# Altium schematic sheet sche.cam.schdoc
size 297 x 209 mm; Width: 1170; Height: 825; Symbol: Sheet-Symbol_A4; Company: 嘉立创EDA; Version: V1.0; Page Size: A4; @Project Name: 木马派(Mumap) Linux卡片电脑-RV1106G; @Page Count: 10; @Update Date: 2024-12-29; @Create Date: 2024-11-27; @Schematic Name: Schematic1; @Page No: 8; @Page Name: CSI; Border: 1; Title Block Position: 3; Region Start: 1; X Region Count: 6; Y Region Count: 4; Blade Width: 10; Title Block: 1; @Board Name: NandFlash; @Create Time: 22:20:09; @Update Time: 16:11:56; Device: Sheet-Symbol_A4
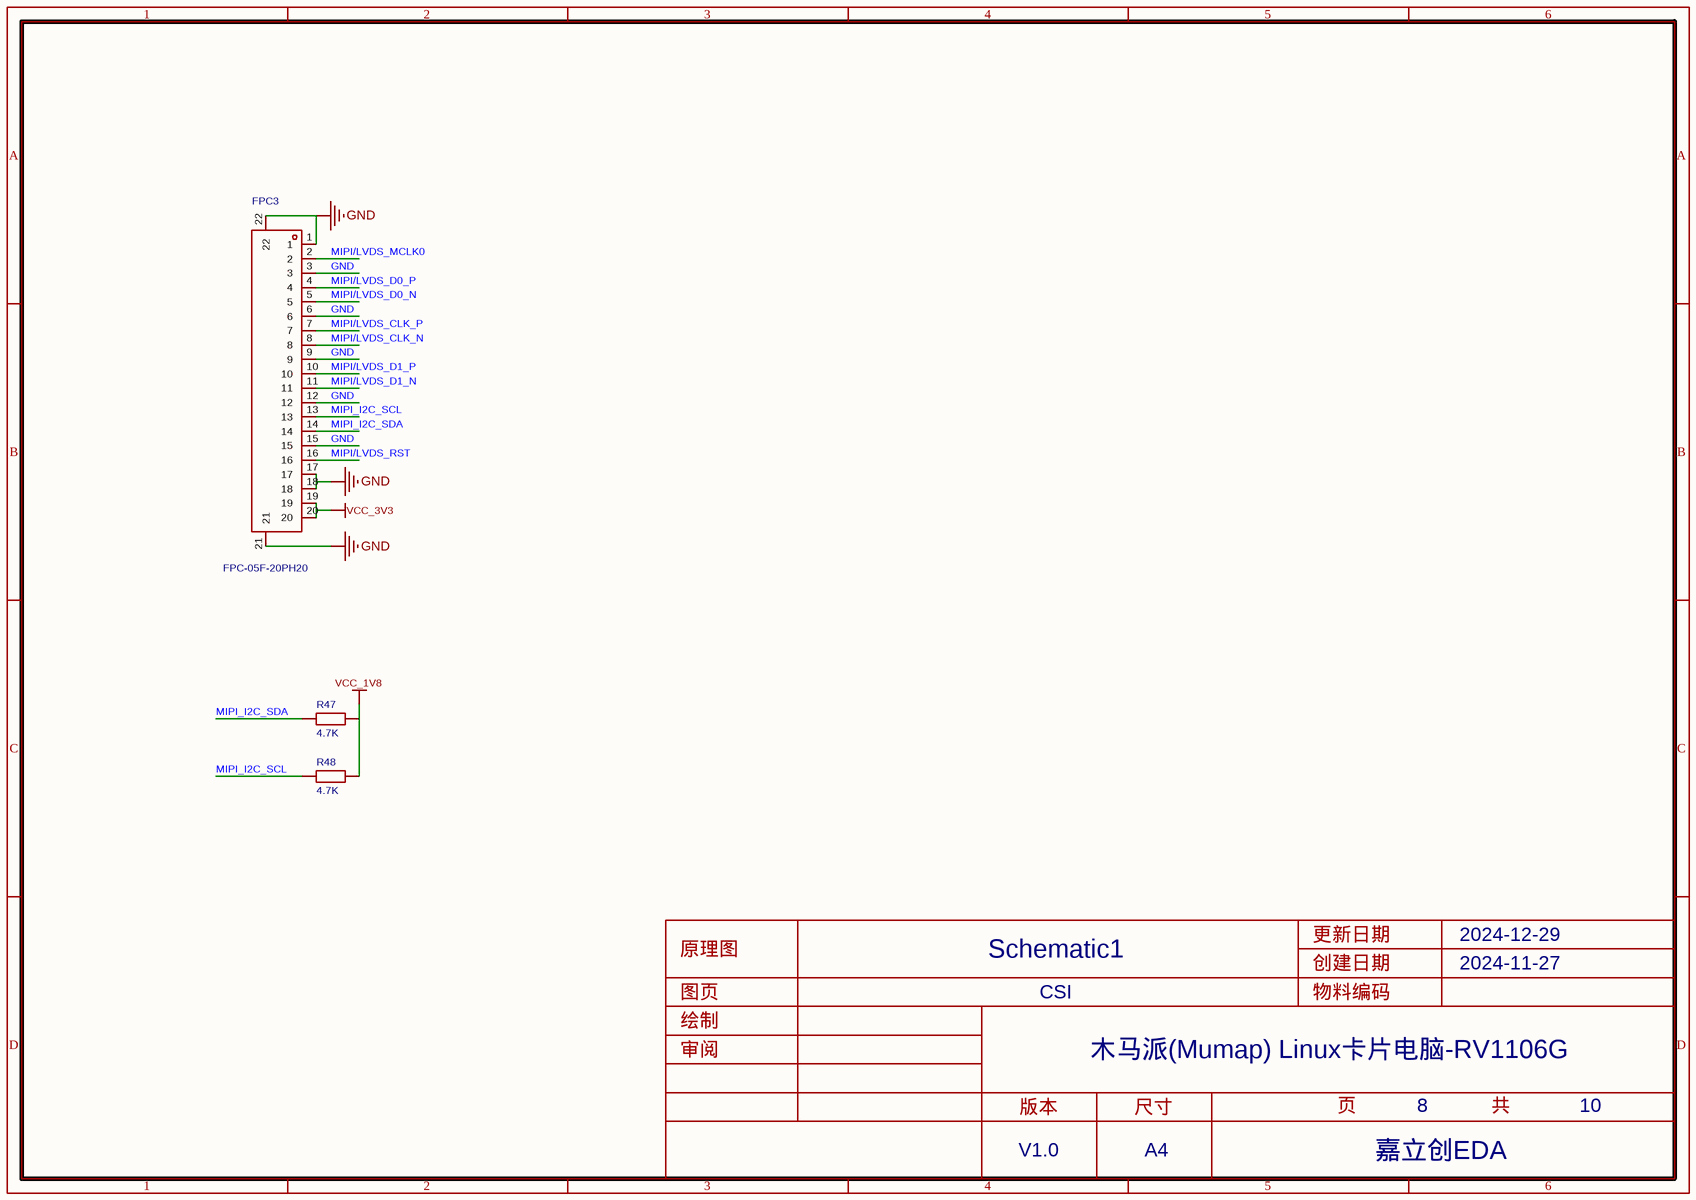
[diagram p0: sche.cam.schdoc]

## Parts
FPC3  FPC-05F-20PH20  [FPC-SMD_20P-P0.50_XUNPU_FPC-05F-20PH20]
R47  4.7K  [R0402]
R48  4.7K  [R0402]

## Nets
GND: FPC3.1 FPC3.3 FPC3.6 FPC3.9 FPC3.12 FPC3.15 FPC3.17 FPC3.18 FPC3.21 FPC3.22
VCC_1V8: R47.2 R48.2
VCC_3V3: FPC3.19 FPC3.20
MIPI/LVDS_CLK_N: FPC3.8
MIPI/LVDS_CLK_P: FPC3.7
MIPI/LVDS_D0_N: FPC3.5
MIPI/LVDS_D0_P: FPC3.4
MIPI/LVDS_D1_N: FPC3.11
MIPI/LVDS_D1_P: FPC3.10
MIPI/LVDS_MCLK0: FPC3.2
MIPI/LVDS_RST: FPC3.16
MIPI_I2C_SCL: FPC3.13 R48.1
MIPI_I2C_SDA: FPC3.14 R47.1

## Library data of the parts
FPC3 = FPC-05F-20PH20: 锁定特性:翻盖式;触点类型:下接;触点数量:20P;间距:0.5mm;安装类型:卧贴;工作温度范围:-25℃~+85℃;; Manufacturer: XUNPU(讯普); AddInBom: yes; ModelId: 73968c39cc2b4cd8b63034a0fc5a76ca; ModelTransform: 566.928,201.5744,0,0,0,0,0.004,-51.182,0; Locking Feature: 翻盖式; Number of Contacts: 20P; Pitch: 0.5mm; FFC, FCB Thickness: 0.3mm
R47 R48 = Res_0402: Symbol: 电阻; ConvertToPcb: yes; ModelId: 671aefced39d4c318694bba8bd8efd39; ModelName: R0402_L1.0-W0.5-H0.5; ModelTransform: 39.37,19.685,0,0,0,0,0,0.0005,0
